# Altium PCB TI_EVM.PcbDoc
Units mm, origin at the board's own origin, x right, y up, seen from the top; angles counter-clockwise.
Board outline 90 x 58.4 mm, 2 copper layers (Top Layer, Bottom Layer); 66 components, 32 nets, 162 pads, 48 vias.
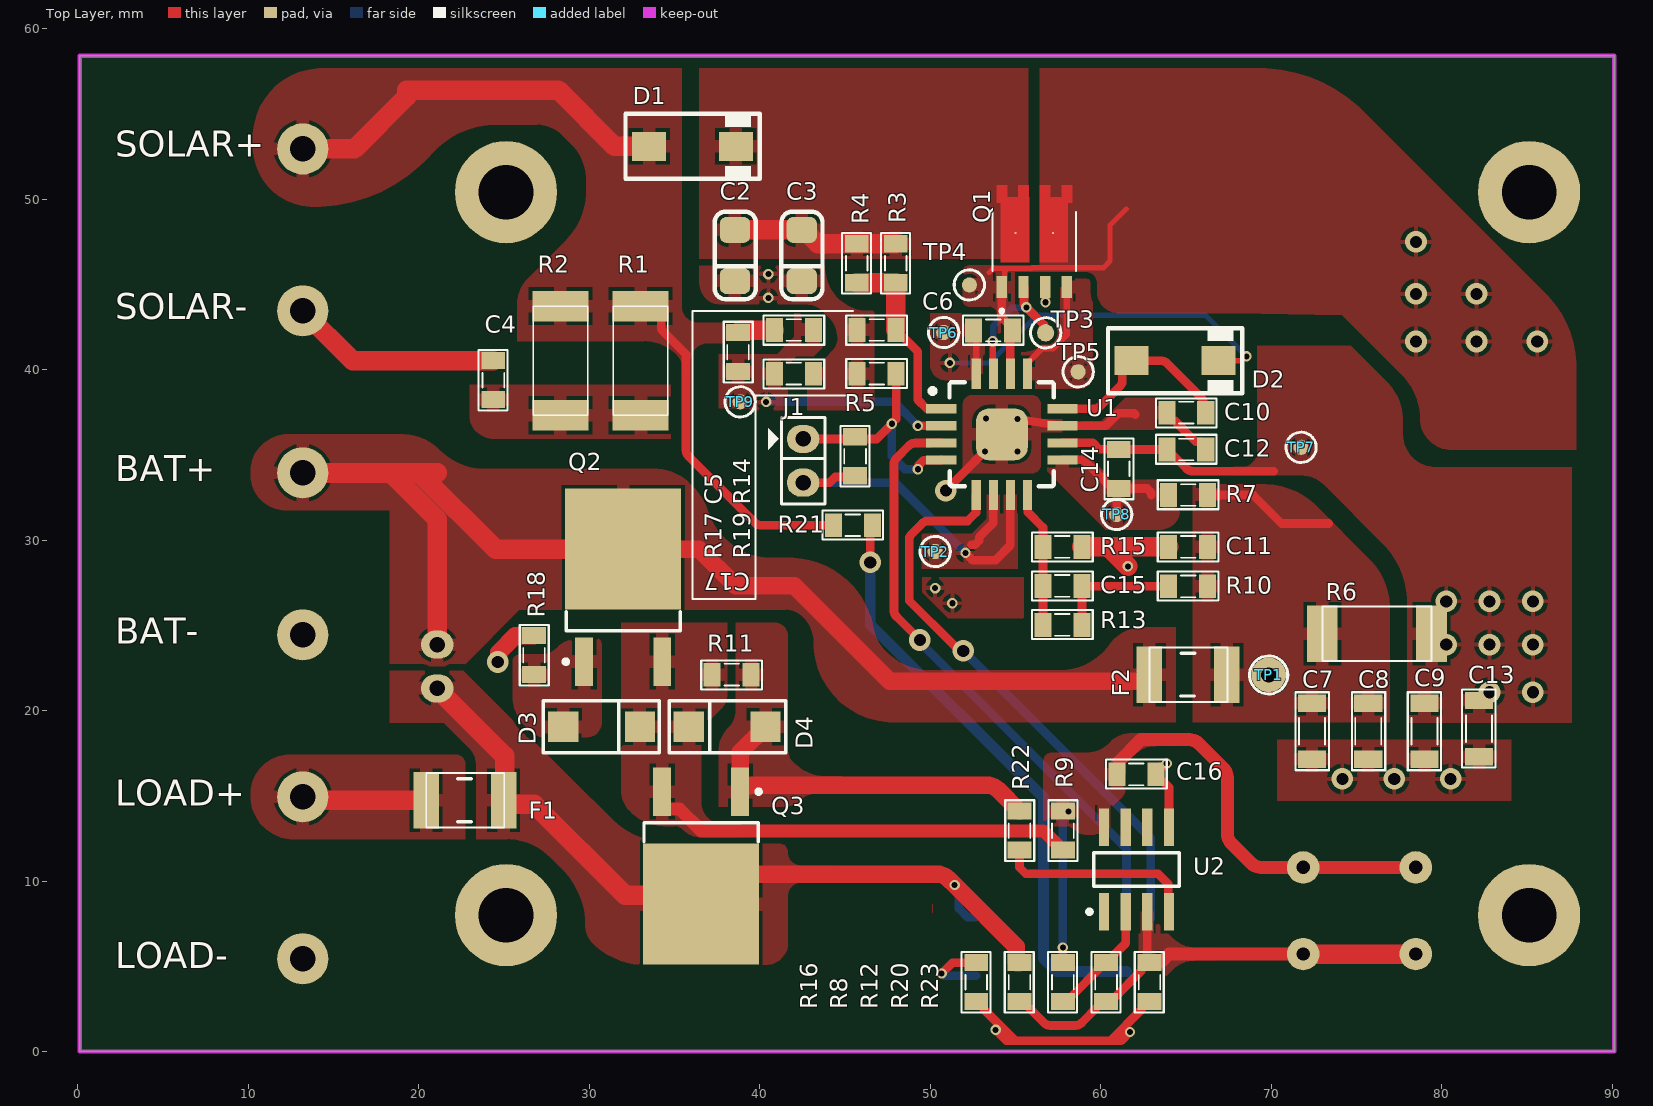
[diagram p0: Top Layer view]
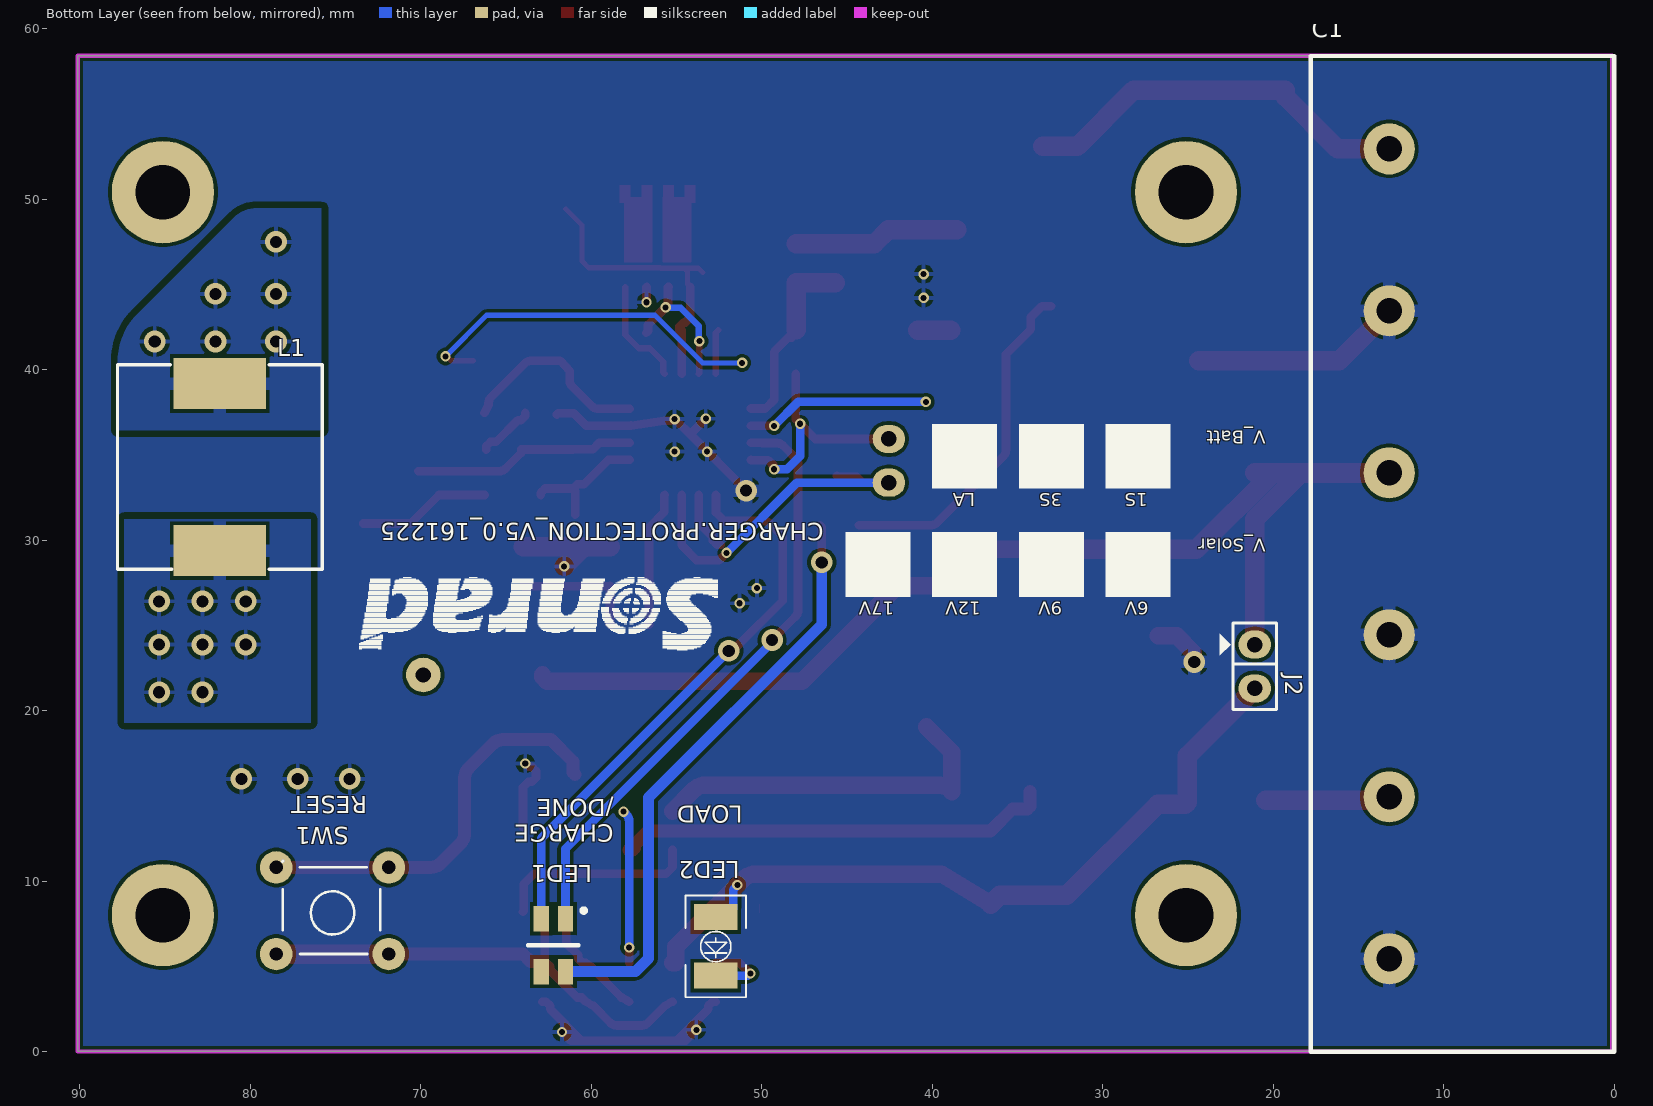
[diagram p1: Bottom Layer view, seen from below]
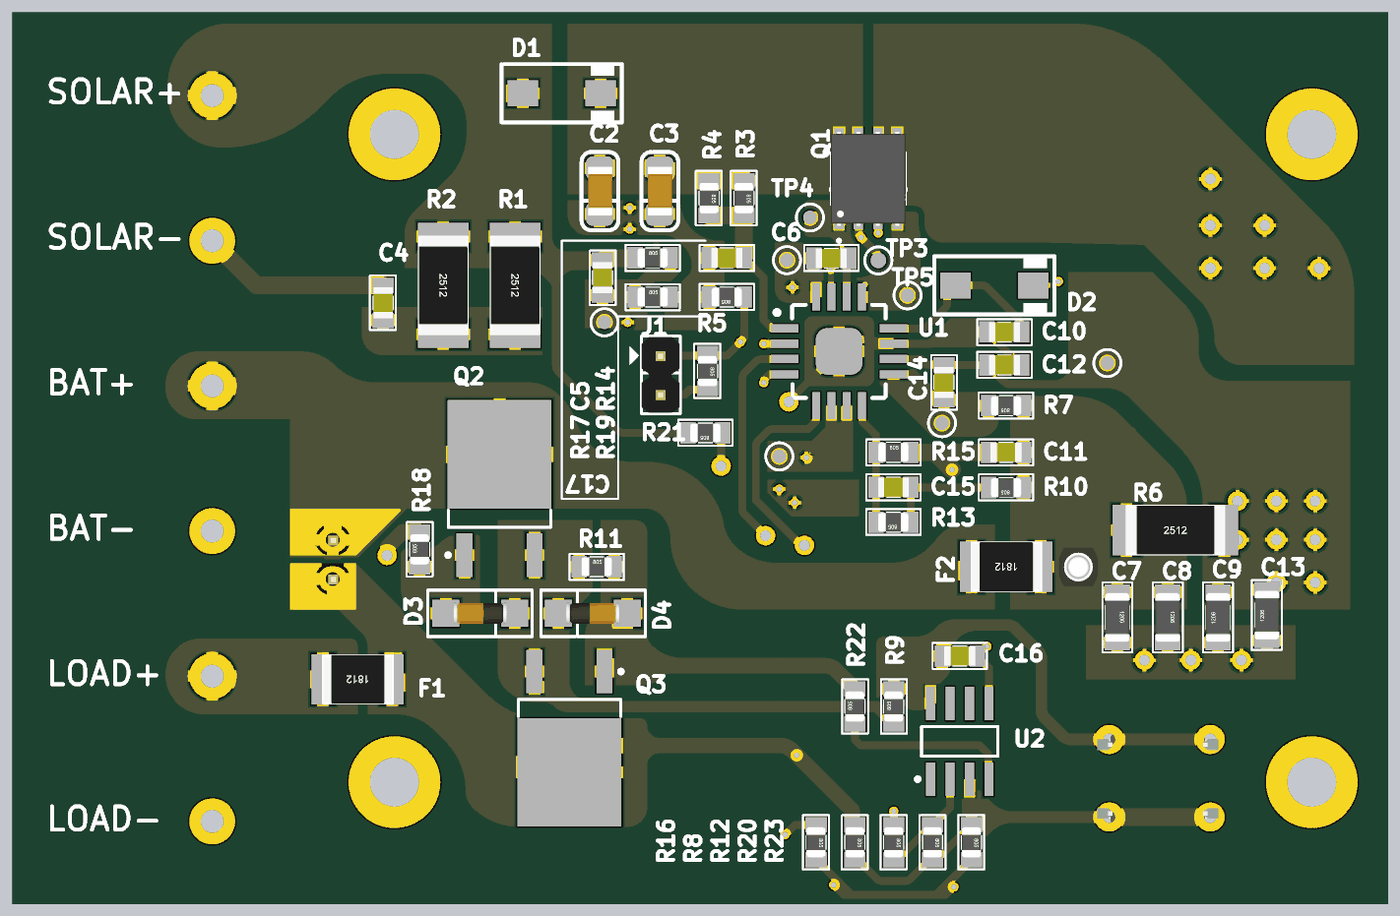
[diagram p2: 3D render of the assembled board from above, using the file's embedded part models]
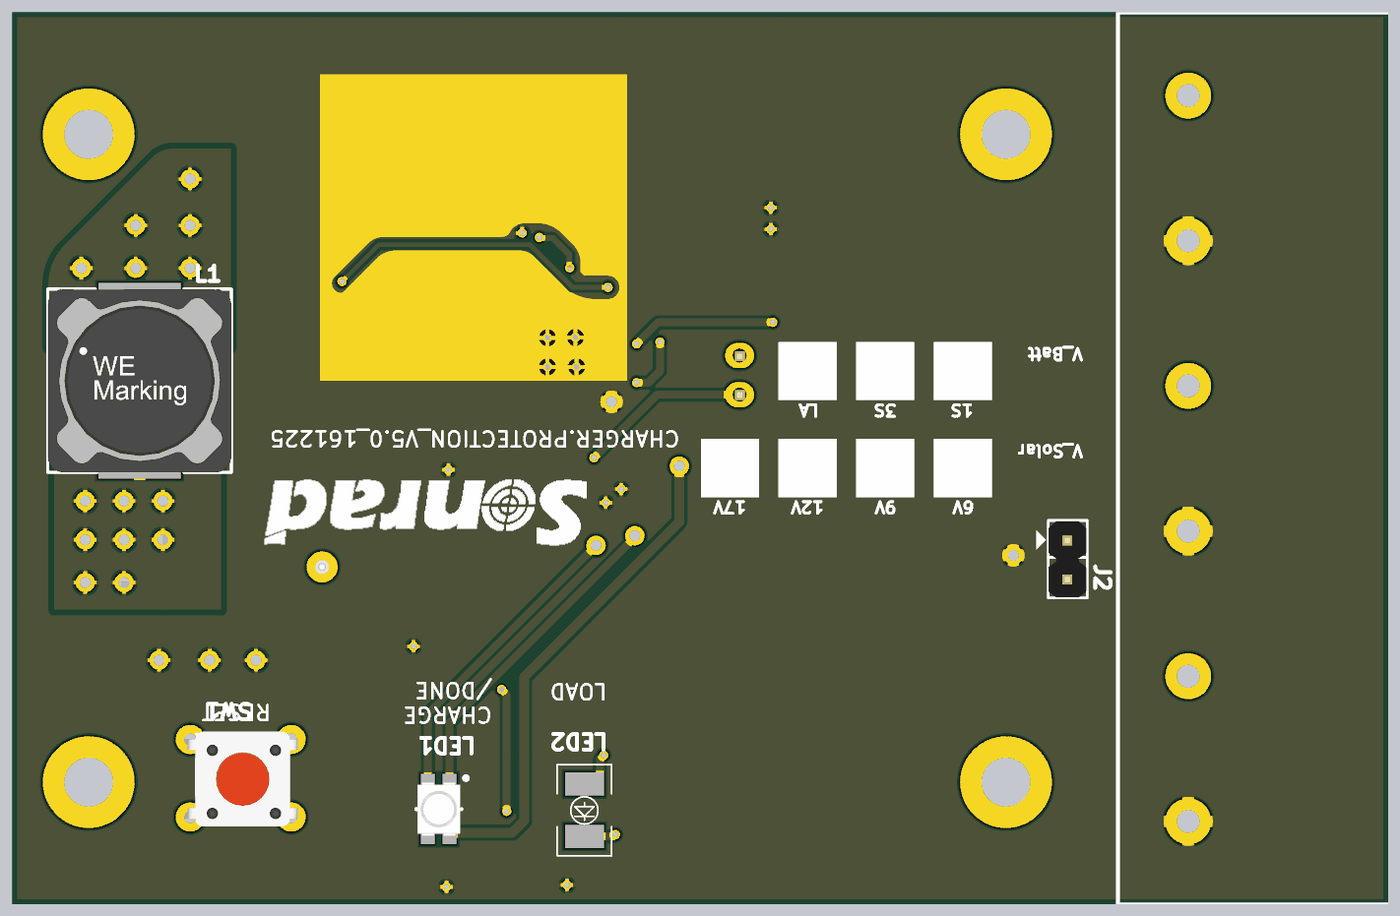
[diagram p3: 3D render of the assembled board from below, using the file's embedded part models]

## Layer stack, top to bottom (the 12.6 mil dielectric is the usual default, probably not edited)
Top Solder: solder mask 0.0102, Solder Resist, Dk 3.5
Top Layer: signal copper 0.0356
Dielectric 1: dielectric 0.32, FR-4, Dk 4.8
Bottom Layer: signal copper 0.0356
Bottom Solder: solder mask 0.0102, Solder Resist, Dk 3.5

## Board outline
0.119,0.016 0.119,58.416 90.119,58.416 90.119,0.016

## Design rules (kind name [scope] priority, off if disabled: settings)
Clearance [All] p1: gap=0.203 ignorepadtopadclearanceinfootprint=FALSE except(0: Arc-Text Track-Text SMDPad-Text SMDPad-Hole THPad-THPad THPad-Text THPad-Hole Via-Text Via-Hole Fill-Text Fill-Hole Poly-Text Poly-Hole Region-Text Region-Hole Text-Text Text-Hole; 0.305: Arc-Via Track-Via SMDPad-Via THPad-Via Via-Via; 0.381: Fill-Fill Fill-Poly Fill-Region Poly-Poly Poly-Region Region-Region)
HoleSize [All] p1: absolutevalues=TRUE maxlimit=3.81 minlimit=0.025 maxpercent=80.000 minpercent=20.000
MinimumSolderMaskSliver [All] p1: minsoldermaskwidth=0
PlaneClearance [All] p1: clearance=0.381
PlaneConnect [All] p1: planeconnectstyle=Relief reliefexpansion=0.762 reliefentries=4 reliefconductorwidth=0.254 reliefairgap=0.254
PolygonConnect [All] p1: connectstyle=Relief reliefconductorwidth=0.762 reliefentries=4 polygonreliefangle="90 Angle" airgapwidth=0.203
RoutingVias [All] p1: holewidth=0.711 width=1.27 viastyle="Through Hole" minholewidth=0.254 minwidth=0.508 maxholewidth=0.711 maxwidth=1.27
SilkToSilkClearance [All] p1: silktosilkclearance=0.025
SilkToSolderMaskClearance [IsPad] p1: minsilkscreentomaskgap=0 clearancetoexposedcopper=TRUE
SolderMaskExpansion [All] p1: expansion=0.102 istentingtop=FALSE
SupplyNets "Schematic Supply Nets_1" [InNet('TERM_EN')] p1: voltage=0.000
SupplyNets "Schematic Supply Nets_5" [InNet('GND')] p2: voltage=0.000
Width [All] p1: maxlimit=1.143 minlimit=0.254 preferedwidth=0.508 bottomlayer_minwidth=0.305 minimp=50.000000 maximp=50.000000 favimp=50.000000
24 further rules are at their usual default settings.

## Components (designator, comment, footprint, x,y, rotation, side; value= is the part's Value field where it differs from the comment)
C1 "JP6" HB9500-6P 17.8,58.4 r270 bottom locked
C2 "10uF" CAP_3216 38.6,46.752 r90 top value=33p
C3 "10uF" CAP_3216 42.515,46.752 r90 top value=33p
C4 "2.2uF" CAP_0805 24.376,39.386 r270 top value=33p
C5 "0.1uF" CAP_0805 46.855,42.332 r0 top value=33p
C6 "1uF" CAP_0805 53.691,42.307 r180 top value=33p
C7 "4.7uF" CAP_1206 72.39,18.796 r270 top value=33p
C8 "1uF" CAP_1206 75.692,18.796 r270 top value=33p
C9 "10uF" CAP_1206 78.994,18.796 r90 top value=33p
C10 "10uF" CAP_0805 65.016,37.481 r0 top value=33p
C11 "0.1uF" CAP_0805 65.121,29.607 r0 top value=33p
C12 "10uF" CAP_0805 65.016,35.322 r180 top value=33p
C13 "10uF" CAP_1206 82.185,18.953 r90 top value=33p
C14 "10uF" CAP_0805 61.057,34.179 r90 top value=33p
C15 "0.1uF" CAP_0805 57.755,27.321 r0 top value=33p
C16 "0.47uF" CAP_0805 62.095,16.272 r180 top value=33p
C17 "22pF" CAP_0805 38.727,41.037 r90 top value=33p
D1 "1N5824" SMA 36.06,53.102 r0 top value="Diode c?m 1N5408"
D2 "1N5819" SMA 64.359,40.529 r0 top value="Diode c?m 1N5408"
D3 "Zenner 12V" DIODE_ZENER_SMD 30.726,19.066 r0 top
D4 "Zenner 12V" DIODE_ZENER_SMD 38.092,19.066 r180 top
F1 "F5A" RES-SMD-1812 22.979,14.748 r180 top value=Fuse
F2 "F5A" RES-SMD-1812 65.397,22.114 r180 top value=Fuse
J1 "Jumper 2" JP2 42.545,35.941 r270 top value="JP 2"
J2 "Jumper 2" JP2 21.082,23.876 r270 bottom value="JP 2"
L1 "15uH" L-SMD-M-12x10 81.788,34.29 r180 bottom value="150 mH"
LED1 "LED RGB SMD v1" "LED RGB 3528" 62.222,6.249 r270 bottom locked
LED2 "LED" "LED 3512" 52.697,7.89 r270 bottom locked value="LED 3 - 5 ly 2 Colour"
Q1 "SI7288" "SO-8 dual" 56.104,47.517 r90 top
Q2 "Sud50p06" TO-252 31.992,27.076 r90 top
Q3 "Sud50p06" TO-252 36.564,11.056 r270 top
R1 "2R" RES-SMD-2512 32.885,40.529 r270 top
R2 "2R" RES-SMD-2512 28.186,40.529 r270 top
R3 "10R" RES-SMD-0805 47.976,46.244 r270 top
R4 "NC" RES-SMD-0805 45.69,46.244 r270 top
R5 "10k" RES-SMD-0805 45.593,34.925 r270 top
R6 "0.05" RES-SMD-2512 76.2,24.384 r0 top
R7 "0R" RES-SMD-0805 65.121,32.655 r180 top
R8 "DFN" RES-SMD-0805 55.237,4.08 r270 top
R9 "10R" RES-SMD-0805 57.777,12.97 r90 top
R10 "0R" RES-SMD-0805 65.121,27.296 r180 top
R11 "1M" RES-SMD-0805 38.346,22.114 r0 top
R12 "100k" RES-SMD-0805 57.777,4.08 r270 top
R13 "499k" RES-SMD-0805 57.755,25.035 r180 top
R14 "10k" RES-SMD-0805 46.855,39.767 r180 top
R15 "100k" RES-SMD-0805 57.755,29.607 r0 top
R16 "10k" RES-SMD-0805 52.697,4.08 r270 top
R17 "499k" RES-SMD-0805 42.007,42.332 r0 top
R18 "100k" RES-SMD-0805 26.764,23.257 r90 top
R19 "36k" RES-SMD-0805 42.007,39.767 r0 top
R20 "1M" RES-SMD-0805 60.317,4.08 r270 top
R21 "1k" RES-SMD-0805 45.458,30.877 r180 top
R22 "100R" RES-SMD-0805 55.237,12.97 r90 top
R23 "115k" RES-SMD-0805 62.857,4.08 r270 top
SW1 "SW" SW4 71.874,5.731 r0 bottom locked value="Button chip 4 pin"
TP1 "TP" TP1 69.85,22.098 r0 top value="Test Point"
TP2 "TP" "Testpoint 50ml"#1 50.292,29.337 r0 top value="Test Point"
TP3 "TP" "Testpoint 50ml"#2 56.769,42.164 r0 top value="Test Point"
TP4 "TP" "Testpoint 50ml"#1 52.294,44.974 r0 top value="Test Point"
TP5 "TP" "Testpoint 50ml"#1 58.674,39.878 r0 top value="Test Point"
TP6 "TP" "Testpoint 50ml"#1 50.792,42.18 r0 top value="Test Point"
TP7 "TP" "Testpoint 50ml"#1 71.747,35.449 r0 top value="Test Point"
TP8 "TP" "Testpoint 50ml"#1 60.93,31.512 r0 top value="Test Point"
TP9 "TP" "Testpoint 50ml"#1 38.854,38.116 r0 top value="Test Point"
U1 "BQ24650" VQFN-16 54.199,36.211 r270 top
U2 "MAX8212" SOIC-8 62.095,10.684 r90 top

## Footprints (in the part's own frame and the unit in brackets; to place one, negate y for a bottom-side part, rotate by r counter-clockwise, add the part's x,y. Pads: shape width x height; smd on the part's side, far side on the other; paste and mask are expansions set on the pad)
CAP_0805 [mil]
  rect 39.37x55 smd: 1(-45,0) 2(45,0)
  silkscreen extent -70,-34 70,33, body extent -40,-25 40,25, height 24
CAP_1206 [mil]
  rect 40x65 smd: 1(-65,0) 2(65,0)
  silkscreen extent -90,-38 90,39, body extent -63,-31 63,32, height 40
CAP_3216 [mil]
  rrect50% 60x70 smd: 1(-60.99,2) 2(56.99,2)
  silkscreen extent -103,-46 99,49, body extent -65,-30 61,32, height 39
DIODE_ZENER_SMD [mil]
  rect 70x70 smd: 1(-88.58,0) 2(88.58,0)
  silkscreen extent -135,-60 134,60, body extent -69,-29 69,29, height 57
HB9500-6P [mm]
  round 3 hole 1.5: 1(5.45,4.6) 2(14.95,4.6) 3(24.45,4.6) 4(33.95,4.6) 5(43.45,4.6) 6(52.95,4.6)
  silkscreen extent 0,0 58.4,17.8
JP2 [mil]
  oval 65x75 hole 36: 1(0,0) 2(101,0)
  silkscreen extent -50,-81 150,50, body extent -48,-50 148,48, height 323
L-SMD-M-12x10 [mm] "WE-PDA SMD Shielded Power Inductor, 1210"
  rect 5.4x3 smd: 1(0,4.9) 2(0,-4.9)
  silkscreen extent -6,-6 6,6, body extent -6,-6 6,6, height 9.7
"LED 3512" [mil]
  rect 60x100 smd: 1(-0.2,0) 2(134.8,0)
  silkscreen extent -50,-70 185,70, body extent -20,-60 155,60, height 75
"LED RGB 3528" [mm]
  rect 1.5x0.9 smd: 1(1.55,0.707) 2(1.55,-0.71) 3(-1.55,0.707) 4(-1.55,-0.707)
  silkscreen extent -2.15,-1.5 0.03,1.9, body extent -1.75,-1.4 1.75,1.4, height 1.87
RES-SMD-0805 [mil]
  rect 39.37x55 smd: 1(-45,0) 2(45,0)
  silkscreen extent -70,-34 70,33, body extent -39,-25 39,25, height 31
RES-SMD-1812 [mm] "Chip Capacitor, Body 3.2x2.5mm, IPC Medium Density"
  rect 1.5x3.3 smd: 1(-1.996,0) 2(2.54,0)
  silkscreen extent -2.04,-1.6 2.54,1.6, body extent -2,-1.6 2.5,1.6, height 0.6
RES-SMD-2512 [mm] "Chip Capacitor, Body 3.2x2.5mm, IPC Medium Density"
  rect 1.8x3.3 smd: 1(-3.2,0.127) 2(3.2,0.127)
  silkscreen extent -3.2,-1.47 3.2,1.73, body extent -3.2,-1.47 3.2,1.73, height 0.6
SMA [mm]
  rect 2x1.7 smd: 1(-2.544,0) 2(2.544,0)
  silkscreen extent -3.94,-1.9 3.94,1.91, body extent -2.87,-1.4 2.87,1.4, height 2.29
"SO-8 dual" [mm] "Dual N-channel"
  rect 1.27x0.61 smd: 1(-2.67,1.905) 2(-2.67,0.635) 3(-2.67,-0.635) 4(-2.67,-1.905)
  rect 0.1x0.1 smd paste-1 mask+0: 5_6_10(0.5,-1.1) 7_8_9(0.5,1.1)
  Top Layer region: 2.6,-0.33 3.305,-0.33 3.305,-0.94 2.6,-0.94 2.6,-1.6 3.305,-1.6 3.305,-2.21 2.285,-2.21 2.285,-1.955 -1.215,-1.955 -1.215,-0.305 2.6,-0.305
  Top Layer region: 3.305,1.6 2.6,1.6 2.6,0.94 3.305,0.94 3.305,0.33 2.6,0.33 2.6,0.305 -1.215,0.305 -1.215,1.955 2.285,1.955 2.285,2.21 3.305,2.21
  silkscreen extent -4.17,-2.45 1.72,2.45, body extent -3.07,-2.58 3.07,2.58, height 1.12
SOIC-8 [mm] "SOIC, 8-Leads, Body 5,0x4,0mm (max), Pitch 1,27mm, IPC Medium Density"
  rect 2.2x0.6 smd: 1(-2.475,1.905) 2(-2.475,0.635) 3(-2.475,-0.635) 4(-2.475,-1.905) 5(2.475,-1.905) 6(2.475,-0.635) 7(2.475,0.635) 8(2.475,1.905)
  silkscreen extent -2.6,-2.5 0.98,2.88, body extent -3.2,-2.5 3.2,2.5, height 1.75
SW4 [mil] "SW button 4pin, 250 x250 mil"
  round 75 hole 31: 1(0,0) 2(0,-200) 3(260,-200) 4(260,0)
  silkscreen extent 20,-215 245,0, body extent -31,-220 281,24, height 276
"Testpoint 50ml"#1 [mil]
  round 35 smd: 1(0,0)
  silkscreen extent -35,-35 35,35
"Testpoint 50ml"#2 [mil]
  round 40 smd: 1(0,0)
  silkscreen extent -35,-35 35,35
TO-252 [mm] "KVU D-PAK, 3-Pads, Body 6,2x6,7mm (max), IPC Medium Density"
  rect 2.85x1.05 smd: 1(-4.2,2.29) 3(-4.2,-2.29)
  rect 7.1x6.8 smd: 2(2.4,0)
  silkscreen extent -4.32,-3.35 -1.27,3.49, body extent -5.03,-3.35 5.08,3.35, height 2.4
TP1 [mil] "Test point"
  round 80 hole 35: 1(0,0)
  silkscreen extent -44,-44 44,44, body extent -50,-50 50,50, height 178
VQFN-16 [mil]
  rect 21x70 smd: 1(-59.05,-140) 2(-19.68,-140) 3(19.69,-140) 4(59.06,-140) 9(59.06,140) 10(19.69,140) 11(-19.68,140) 12(-59.05,140)
  rect 70x21 smd: 5(140,-59.05) 6(140,-19.68) 7(140,19.69) 8(140,59.06) 13(-140,59.06) 14(-140,19.69) 15(-140,-19.68) 16(-140,-59.05)
  rrect50% 120x120 smd: 17(0,0)
  silkscreen extent -120,-164 120,120, body extent -118,-118 118,118, height 31

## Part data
C1: "WR-PHD 2.54 mm Angled Socket Header", Manufacturer="W¨¹rth Elektronik eiSos GmbH", partNo=613006143121
C2 C3: library part CapSMD, "Capacitor"
C4 C5 C6 C10 C11 C12 C14 C15 C16 C17: library part CapSMD, "C_0805"
C7 C8 C9 C13: library part CapSMD, "C_1206"
D1: library part 1N5822, "SS54 Diode Schottky 5A 40V"
D2: library part 1N5822, "S4 Diode Schottky 1A 40V"
D3 D4: library part Zenner, "generic zenner diode"
F1 F2: library part Fuse, "Fuse 5A"
J1 J2: library part "JP 2"
L1: library part Inductor, "Inductor"
LED2: library part "LED SMD"
Q1: library part "Dual MOSFET-N", "Si7288"
Q2 Q3: library part MOSFET-P
R1 R2 R6: library part "Resistor - SMD", "R_2512", Manufacturer="Generic Components"
R3 R4 R5 R7 R8 R9 R10 R11 R12 R13 R14 R15 R16 R17 R18 R19 R20 R21 R22 R23: library part "Resistor - SMD", "R_0805", Manufacturer="Generic Components"
SW1: library part SW4, "Switch button 4 pin"
TP1: library part TP1, "Test Point"
TP2 TP3 TP4 TP5 TP6 TP7 TP8 TP9: library part TP_1, "Test Point"
U1: "BQ24650 Stand-Alone Synchronous Buck Battery Charge Controller for Solar Power / With Maximum Power Point Tracking"
U2: "Microprocessor Voltage Monitors  / with Programmable Voltage Detection"

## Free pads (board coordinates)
  round 6 hole 3.2: 14(25.119,8.016) 14(25.119,50.416) 14(85.119,8.016) 14(85.119,50.416)

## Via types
v1: diameter 0.61, hole 0.356, Top Layer to Bottom Layer, 26 vias
v2: diameter 1.27, hole 0.711, Top Layer to Bottom Layer, 22 vias

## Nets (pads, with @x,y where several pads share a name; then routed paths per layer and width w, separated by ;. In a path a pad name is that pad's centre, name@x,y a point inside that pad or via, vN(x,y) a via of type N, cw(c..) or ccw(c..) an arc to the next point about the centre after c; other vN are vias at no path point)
BTST: C6.2 D2.2 TP6.1 U1.16 | length 23.9
  Top Layer w0.305: D2.2 68.231,40.529 68.485,40.783 v1(68.55,40.783)
  Top Layer w0.381: C6.2 52.699,42.156 U1.16
  Bottom Layer w0.305: v1(51.151,40.402) 53.459,40.402 56.253,43.196 66.137,43.196 v1(68.55,40.783)
GND: C1.2 C1.4 C1.6 C2.1 C3.1 C4.1 C5.1 C7.2 C8.2 C9.1 C10.1 C11.1 C12.1 C13.1 C16.1 Q1.3 R14.2 R15.2 R16.2 R18.2 R19.2 R23.2 U1.11 U1.17 U2.5 | length 60.6
  Top Layer w0.508: v2(50.919,32.909) 50.919,32.931 U1.17 ; R16.2 52.895,2.937 53.141,2.691 53.141,2.493 54.983,0.651 ; v1(53.282,37.128) U1.17 ; v1(53.84,1.286) 54.475,0.651 54.983,0.651 ; U1.17@54.998,37.01 U1.17@55.015,37.01 ; v1(55.11,37.1) U1.17@55.015,37.01 ; Q1.3 56.761,44.825 v1(56.761,43.958) ; v1(61.714,1.159) 61.206,0.651 60.571,0.651 ; 62.016,37.375 61.952,37.439 61.908,37.439 61.9,37.447 61.023,37.447 60.287,36.711 U1.11 57.669,36.724 55.732,37.008 55.706,37.009 ccw(c55.685,36.502) 55.685,37.01 55.11,37.01 U1.17@55.015,37.01 ; R23.2 62.659,2.937 62.412,2.691 62.412,2.493 60.571,0.651 ; v1(63.873,16.907) 63.846,16.907 63.655,16.717 63.484,16.717 63.238,16.471 C16.1 63.238,16.074 63.484,15.828 63.683,15.828 64,15.51 U2.5 ; C10.1 63.873,37.283 64.119,37.037 64.317,37.037 65.587,35.767 65.913,35.767 66.159,35.521 C12.1 ; U1.17 54.961,36.959 U1.17@55.015,37.01 ; 54.983,0.651 60.571,0.651
  Top Layer w1.016: v2(24.638,22.86) 24.687,22.909 24.687,23.417 25.67,24.4 R18.2
  Top Layer w1.143: C1.2 16.121,40.529 C4.1 ; R15.2 60.571,29.607 ; v1(61.587,28.464) 60.571,29.48 60.571,29.607 ; C11.1 60.571,29.607
  other v1: 51.3,26.305 50.284,27.194 53.205,35.195 55.11,35.195 40.505,44.212 40.505,45.609
  other v2: 74.168,16.002 77.216,16.002 80.518,16.002
HIDRV: Q1.2 TP3.1 U1.15 | length 8.4
  Top Layer w0.381: v1(53.658,41.678) 53.679,41.658 53.679,39.788 U1.15
  Top Layer w0.508: Q1.2 55.498,44.818 55.498,43.83 55.64,43.688 v1(55.64,43.66) ; v1@55.659,43.641 56.672,42.628 56.672,42.261 TP3.1
  Bottom Layer w0.381: v1(53.658,41.678) 53.685,41.706 53.685,42.555 54.763,43.633 55.613,43.633 v1(55.64,43.66)
LODRV: Q1.4 TP5.1 U1.13 | length 6.4
  Top Layer w0.381: U1.13 55.776,39.843 55.776,40.466 56.57,41.26 57.215,41.26 58.009,42.054 Q1.4
MPPSET: C17.1 R17.2 R19.1 TP9.1 U1.2 | length 10.9
  Top Layer w0.508: v1(49.276,36.703) 49.284,36.711 U1.2
  Bottom Layer w0.508: v1(40.378,38.116) 47.863,38.116 v1(49.276,36.703)
NetC1_5: C1.5 F1.2 | length 7.4
  Top Layer w1.143: C1.5 13.2,14.748 F1.2
NetC2_2: C2.2 C3.2 D1.2 Q1.7_8_9 R3.1 R4.1 | length 9.8
  Top Layer w1.143: C2.2 C3.2 42.591,48.2 43.404,47.387 R4.1 R3.1
NetC4_2: C4.2 R1.2 R2.2
NetC5_2: C5.2 R3.2 R4.2 U1.1 | length 11.4
  Top Layer w0.508: C5.2@47.976,42.354 47.976,42.156 48.244,41.888 48.442,41.888 49.268,41.062 49.268,38.243 49.787,37.724 50.63,37.724 U1.1
  Top Layer w1.143: R4.2 R3.2 C5.2@47.976,42.354
NetC7_1: C7.1 C8.1 C11.2 F2.1 R6.1 R7.1 R10.1 TP1.1 | length 7.8
  Top Layer w0.508: R7.1 68.931,32.655 70.607,30.979 73.376,30.979
NetC10_2: C10.2 D2.1 U1.12 | length 11.6
  Top Layer w0.508: U1.12 59.598,37.711 ccw(c59.598,38.219) 59.903,37.812 ccw(c59.598,38.219) 59.957,37.859 61.119,39.021 ccw(c60.759,39.379) 61.267,39.379 61.267,39.933 D2.1 63.528,40.529 cw(c63.528,40.021) 63.886,40.381 65.878,38.389 cw(c65.518,38.031) 66.026,38.031 66.026,37.926 C10.2@66.264,37.481
NetC15_1: C15.1 R13.2 R15.1 U1.8 | length 8
  Top Layer w0.508: U1.8 55.712,32.642 55.712,31.65 56.612,30.75 R13.2
NetC15_2: C15.2 R10.2 R13.1 | length 7.3
  Top Layer w0.508: R13.1 58.898,26.851 C15.2 ; C15.2@58.924,27.296 R10.2
NetC16_2: C16.2 R9.2 R12.1 SW1.2 SW1.3 U2.8 | length 33
  Top Layer w0.508: R12.1 v1(57.777,6.112)
  Top Layer w0.762: C16.2 61.071,16.391 61.071,17.026 62.349,18.304 65.2,18.304 cw(c65.2,17.542) 65.658,18.152 cw(c65.2,17.542) 65.739,18.081 67.206,16.614 cw(c66.667,16.075) 67.277,16.533 cw(c66.667,16.075) 67.429,16.075 67.429,12.77 ccw(c68.191,12.77) 67.581,12.312 ccw(c68.191,12.77) 67.652,12.231 68.849,11.034 ccw(c69.388,11.573) 68.93,10.963 ccw(c69.388,11.573) 69.388,10.811 SW1.2 SW1.3
  Bottom Layer w0.508: v1(57.777,6.112) 57.777,13.537 cw(c58.285,13.537) 57.925,13.896 v1@58.091,14.062
  other v1: 58.111,14.082
NetD3_1: D3.1 Q2.1 R18.1
NetD3_2: D3.2 D4.2 Q2.3 Q3.3 R9.1 R11.1 | length 25.6
  Top Layer w0.762: Q3.3 34.274,14.379 34.418,14.235 35.295,14.235 36.573,12.957 56.647,12.957 57.459,12.144 57.459,11.946 57.579,11.827 R9.1
NetD4_1: D4.1 Q3.1 R11.2 R22.2 | length 21.5
  Top Layer w1.016: Q3.1@38.854,15.62 Q3.1 38.871,15.401 39.278,15.564 cw(c39.656,14.621) 39.656,15.637 53.292,15.637 cw(c53.292,14.621) 54.011,15.339 R22.2 ; Q3.1@38.854,15.637 38.854,17.578 D4.1
NetJ1_1: J1.1 R5.1 R14.1 U1.4 | length 14.1
  Top Layer w0.508: J1.1 46.863,35.941 v1(47.752,36.83) 47.752,36.857 47.998,37.104 R14.1 ; v1(49.276,34.163) 49.295,34.182 49.295,34.369 49.624,34.698 50.63,34.698 U1.4
  Bottom Layer w0.508: v1(47.752,36.83) 47.752,34.925 48.514,34.163 v1(49.276,34.163)
NetLED1_1: LED1.1 R21.1 | length 34.9
  Top Layer w0.508: v2(46.482,28.702) 46.482,30.758 R21.1
  Bottom Layer w0.635: v2(46.482,28.702) 46.482,25.062 56.634,14.91 56.634,5.477 57.412,4.699 LED1.1
NetLED1_3: LED1.3 U1.3 | length 35.7
  Top Layer w0.508: v2(49.395,24.146) 48.02,25.521 48.019,25.522 cw(c48.379,25.88) 47.973,25.576 cw(c48.379,25.88) 47.871,25.88 47.871,34.453 cw(c48.379,34.453) 47.973,34.757 cw(c48.379,34.453) 48.019,34.811 48.758,35.55 cw(c49.117,35.19) 49.117,35.698 50.008,35.698 U1.3
  Bottom Layer w0.508: v2(49.395,24.146) 49.395,24.019 55.64,17.774 61.514,11.899 LED1.3
NetLED1_4: LED1.4 U1.5 | length 33.9
  Top Layer w0.508: v2(51.935,23.511) 51.729,23.511 51.357,23.882 51.347,23.882 48.76,26.469 48.76,30.008 cw(c49.268,30.008) 48.862,30.312 cw(c49.268,30.008) 48.908,30.366 49.525,30.983 cw(c49.883,30.623) 49.579,31.029 cw(c49.883,30.623) 49.883,31.131 52.189,31.131 52.687,31.629 52.687,32.642 U1.5
  Bottom Layer w0.508: v2(51.935,23.511) 62.929,12.517 LED1.4
NetLED2_2: LED2.2 R16.1 | length 4.4
  Top Layer w0.508: v1(50.665,4.588) 51.3,5.223 R16.1
  Bottom Layer w0.508: v1(50.665,4.588) 50.692,4.588 50.814,4.466 LED2.2
NetR8_2: R8.2 R20.2 R23.1 SW1.1 SW1.4 U2.3 | length 28.6
  Top Layer w0.508: R8.2 55.681,2.691 56.685,1.688 ccw(c57.043,2.048) 56.738,1.642 ccw(c57.043,2.048) 57.043,1.54 58.511,1.54 ccw(c58.511,2.048) 58.816,1.642 ccw(c58.511,2.048) 58.869,1.688 59.872,2.691 R20.2 60.563,3.183 60.817,3.183 62.412,4.779 62.412,4.977 62.659,5.223 R23.1 62.73,5.35 U2.3
  Top Layer w0.762: R23.1 62.917,5.283 63.552,5.283 64,5.731 SW1.1
  Top Layer w1.143: SW1.1 SW1.4
NetR12_2: R12.2 R20.1 U2.2 | length 7
  Top Layer w0.508: R12.2 58.221,3.183 60.015,4.977 R20.1 60.515,5.223 60.761,5.469 60.761,5.668 61.46,6.366 U2.2
NetR22_1: R22.1 U2.4 | length 11.8
  Top Layer w0.508: R22.1 55.237,10.811 55.618,10.43 63.365,10.43 63.954,9.841 63.954,8.255 U2.4
PH: C6.1 L1.1 Q1.1 Q1.5_6_10 TP4.1 U1.14 | length 17.6
  Top Layer w0.305: 53.462,45.697 53.712,45.946 54.537,45.946 ; Q1.1 54.352,45 54.352,45.762 54.537,45.946 ; 61.491,49.419 60.549,48.477 60.549,46.371 60.158,45.98 55.98,45.98 55.946,45.946 54.537,45.946
  Top Layer w0.508: Q1.1 54.199,43.049 54.497,42.752 54.588,42.752 54.834,42.506 C6.1 54.699,42.307 U1.14
  other v2: 78.486,41.656 82.042,41.656 85.598,41.656 78.486,44.45 82.042,44.45 78.486,47.498
SRN: C14.1 R7.2 TP8.1 U1.9 | length 7.7
  Top Layer w0.508: U1.9 59.001,34.711 60.43,33.282 60.811,33.282 C14.1 ; TP8.1 60.93,32.909 C14.1 ; 62.962,32.655 62.962,32.79 62.716,33.036 C14.1
SRP: C9.2 C12.2 C13.2 C14.2 L1.2 R6.2 TP7.1 U1.10 | length 13.2
  Top Layer w0.508: U1.10 59.525,35.711 59.894,35.342 61.037,35.342 C14.2 64.105,35.322 64.105,35.123 64.119,35.11 65.029,34.2 ccw(c65.387,34.56) 65.082,34.154 ccw(c65.387,34.56) 65.387,34.052 70.14,34.052
  other v2: 82.804,21.082 85.344,21.082 80.264,23.876 82.804,23.876 85.344,23.876 80.264,26.416 82.804,26.416 85.344,26.416
TERM_EN: J1.2 R5.2 TP2.1 U1.6 U1.7 | length 24.1
  Top Layer w0.508: J1.2 44.094,33.376 44.43,33.711 45.522,33.711 R5.2 ; v1(52.07,29.254) 52.495,28.829 53.824,28.829 54.699,29.704 U1.7 ; 52.421,29.734 52.62,29.734 52.866,29.98 52.866,30.178 53.699,31.012 U1.6
  Bottom Layer w0.508: J1.2 47.949,33.376 v1(52.07,29.254)
V_BATT: C1.3 F2.2 J2.1 Q2.2 | length 79.2
  Top Layer w1.016: Q2.2 36.441,29.476 38.596,27.321 42.029,27.321 47.617,21.733 62.615,21.733 62.857,21.975 F2.2
  Top Layer w1.143: J2.1 21.082,31.242 18.374,33.95 C1.3 ; 21.082,33.95 C1.3 ; Q2.2 24.507,29.476 20.058,33.925 13.225,33.925 C1.3
V_LOAD: F1.1 J2.2 LED2.1 Q3.2 R8.1 | length 46.8
  Top Layer w1.016: Q3.2 39.456,10.414 50.378,10.414 cw(c50.376,9.398) 51.09,10.12 v1(51.435,9.779) 55.046,6.168 55.046,5.231 55.054,5.223 R8.1
  Top Layer w1.143: J2.2 25.04,17.352 25.04,14.626 25.153,14.513 26.77,14.513 32.119,9.164 36.056,9.164 Q3.2
  Bottom Layer w0.508: v1(51.435,9.779) 51.435,9.752 51.681,9.506 51.681,8.403 52.189,7.895 LED2.1
V_SOLAR: C1.1 C17.2 D1.1 R1.1 R2.1 R17.1 R21.2 | length 45.7
  Top Layer w0.508: R1.1 33.579,43.729 34.225,43.083 34.225,42.364 35.679,40.91 35.679,35.277 ccw(c36.187,35.278) 35.827,34.92 39.723,31.024 ccw(c40.08,31.385) 40.078,30.877 R21.2
  Top Layer w1.143: C1.1 16.223,52.95 19.296,56.023 19.296,56.404 28.186,56.404 31.488,53.102 D1.1 ; C17.2@38.91,42.307 R17.1@40.864,42.307
pads on no net: LED1.2 U2.1 U2.6 U2.7

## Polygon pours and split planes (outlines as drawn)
PH on Top Layer "PH_L01_P000" (solid, pour order 0): 78.74,37.146 ccw(c75.21,37.146) 77.706,39.642 74.168,43.18 67.818,43.323 61.057,43.323 cw(c61.057,44.593) 59.787,44.593 59.787,45.101 ccw(c59.152,45.101) 59.152,45.736 54.961,45.736 54.961,44.011 ccw(c56.008,44.011) 55.268,43.27 55.469,43.069 55.469,41.418 54.961,41.418 54.961,40.021 54.453,40.021 54.453,41.418 53.945,41.418 53.945,43.196 ccw(c53.437,43.196) 53.437,43.704 52.294,43.704 cw(c52.294,44.085) 51.913,44.085 51.913,45.736 cw(c52.294,45.736) 52.294,46.117 56.434,46.117 56.434,57.674 68.169,57.674 69.285,57.674 cw(c69.285,48.991) 75.425,55.131 86.044,44.512 cw(c81.603,40.07) 87.884,40.07 87.884,35.306 80.58,35.306 cw(c80.58,37.146)
V_LOAD on Top Layer "NONET_L01_P-001" (solid, pour order 29): 21.471,19.304 18.288,19.304 18.288,22.352 22.614,22.352 24.162,20.804 29.031,15.935 31.278,13.688 ccw(c34.852,17.263) 34.852,12.208 41.132,12.208 cw(c41.132,11.692) 41.648,11.692 ccw(c42.418,11.692) 42.418,10.922 44.442,10.922 44.442,9.906 42.418,9.906 ccw(c42.418,9.136) 41.648,9.136 41.648,6.366 cw(c40.378,6.366) 40.378,5.096 33.249,5.096 cw(c33.249,9.348) 30.242,6.342 cw(c31.374,7.474) 29.773,7.474 ccw(c25.244,7.474) 28.446,10.678 27.709,11.415 ccw(c25.182,8.89) 25.182,12.462 23.36,12.462 23.36,16.86 ccw(c22.019,16.86) 22.967,17.808
V_BATT on Top Layer "NONET_L01_P-001" (solid, pour order 47): 22.606,22.606 25.908,25.908 20.05,31.766 18.293,31.766 18.293,22.611 18.288,22.606
V_BATT on Top Layer "NONET_L01_P-001" (solid, pour order 32): 40.685,28.972 41.713,28.972 cw(c41.714,23.918) 45.287,27.492 cw(c41.716,23.92) 46.623,25.118 ccw(c49.225,25.342) 47.378,23.496 ccw(c50.101,26.218) 50.101,22.368 57.561,22.368 ccw(c57.561,26.014) 60.532,23.901 cw(c62.453,22.536) 62.453,24.892 64.389,24.892 64.389,19.32 47.858,19.32 cw(c47.858,24.006) 43.172,24.006 ccw(c41.07,24.006) 42.556,25.493 ccw(c41.516,24.454) 41.516,25.924 25.011,25.924 20.215,30.72 ccw(c18.294,29.479) 18.293,31.766 12.184,31.766 cw(c12.184,33.798) 10.152,33.798 10.152,34.052 cw(c12.311,34.052) 12.311,36.211 19.011,36.211 cw(c19.012,33.073) 21.232,35.291 ccw(c23.917,37.976) 23.917,34.179 33.87,34.179 cw(c33.871,31.347) 35.874,33.349 36.062,33.161 cw(c33.465,30.563) 36.919,31.814 ccw(c44.236,34.467) 37.149,31.25 ccw(c40.685,32.856)
GND on Top Layer "NONET_L01_P-001" (solid, pour order 46): 84.074,18.288 70.358,18.288 70.358,14.732 84.074,14.732
NetC7_1 on Top Layer "NONET_L01_P-001" (solid, pour order 20): 72.688,31.968 75.73,28.926 cw(c72.755,25.952) 76.962,25.952 76.962,19.32 65.397,19.32 65.397,33.29 69.496,33.29 cw(c69.496,28.775)
BTST on Top Layer "NONET_L01_P-001" (solid, pour order 2): 50.008,43.323 50.008,40.275 ccw(c50.897,40.275) 50.897,39.386 53.183,39.386 53.183,43.323
NetC2_2 on Top Layer "NONET_L01_P-001" (solid, pour order 3): 36.441,57.674 36.441,46.498 55.745,46.498 55.745,57.674
GND on Top Layer "NONET_L01_P-001" (solid, pour order 5): 51.913,37.989 51.913,34.306 ccw(c52.294,34.306) 52.294,33.925 55.977,33.925 ccw(c55.977,34.433) 56.485,34.433 56.485,36.465 63.724,36.465 63.724,38.37 61.438,38.37 60.041,36.973 56.485,36.973 56.485,37.989 ccw(c55.977,37.989) 55.977,38.497 52.421,38.497 ccw(c52.421,37.989)
SRN on Top Layer "NONET_L01_P-001" (solid, pour order 6): 64.635,33.544 64.635,31.766 cw(c63.492,31.766) 63.492,30.623 60.295,30.623 56.866,34.052 56.866,35.068 59.152,35.068 60.676,33.544
TERM_EN on Top Layer "NONET_L01_P-001" (solid, pour order 8): 55.118,33.671 55.118,28.337 49.5,28.337 49.5,30.369 52.421,30.369 53.31,31.258 53.31,33.671
SRP on Top Layer "NONET_L01_P-001" (solid, pour order 9): 78.268,34.859 ccw(c79.641,36.232) 79.641,34.29 87.63,34.29 87.63,19.304 77.978,19.304 77.978,26.354 ccw(c73.11,26.354) 76.552,29.796 73.125,33.223 ccw(c71.738,31.836) 71.738,33.798 67.788,33.798 67.788,34.306 68.296,34.306 ccw(c68.296,35.195) 69.185,35.195 69.185,41.402 74.676,41.402 76.751,39.327 cw(c74.401,36.978) 77.724,36.977 77.724,36.173 ccw(c79.583,36.173)
LODRV on Top Layer "NONET_L01_P-001" (solid, pour order 12): 55.491,41.037 55.342,41.037 55.342,40.275 55.342,38.878 58.771,38.878 ccw(c58.771,39.64) 59.533,39.64 59.533,44.847 ccw(c58.898,44.847) 58.898,45.482 57.628,45.482 57.628,43.122 cw(c56.275,43.121) 57.232,42.165 56.538,41.471 cw(c55.491,42.517)
NetC16_2 on Top Layer "NONET_L01_P-001" (solid, pour order 21): 61.587,17.034 61.953,17.4 cw(c63.216,16.136) 63.216,17.923 64,17.923 64,18.685 61.819,18.685 ccw(c61.819,16.898) 60.556,18.162 60.459,18.065 cw(c59.196,19.329) 59.196,17.542 57.142,17.542 ccw(c57.142,17.034) 56.634,17.034 56.634,13.605 ccw(c57.015,13.605) 57.015,13.224 57.926,13.224 cw(c57.926,12.357) 58.539,12.97 ccw(c59.152,13.583) 59.152,12.716 60.571,12.716 60.571,14.24 61.153,14.822 ccw(c60.107,15.869) 61.587,15.869
NetD3_2 on Top Layer "NONET_L01_P-001" (solid, pour order 25): 32.399,14.091 cw(c33.678,15.37) 31.869,15.37 31.869,25.162 38.092,25.162 38.092,21.024 cw(c36.739,21.023) 37.696,20.067 36.568,18.939 36.568,14.621 ccw(c37.838,14.621) 37.838,13.351 38.854,13.351 38.854,12.589 36.546,12.589 cw(c36.546,14.069) 35.499,13.023 ccw(c35.013,12.537) 35.013,13.224 34.492,13.224 cw(c34.492,16.185)
NetD4_1 on Top Layer "NONET_L01_P-001" (solid, pour order 27): 38.6,25.162 38.6,20.008 cw(c37.247,20.008) 38.204,19.051 ccw(c39.699,17.555) 37.584,17.555 37.584,14.367 41.385,14.367 ccw(c41.385,15.922) 42.484,14.822 cw(c43.225,14.082) 43.225,15.129 44.823,15.129 44.823,16.145 43.965,16.145 cw(c43.965,18.979) 41.961,16.975 cw(c42.717,17.731) 41.648,17.731 41.648,24.4 ccw(c40.886,24.4) 40.886,25.162
NetD3_1 on Top Layer "NONET_L01_P-001" (solid, pour order 28): 25.963,23.32 27.218,23.321 ccw(c27.218,24.584) 28.112,23.691 cw(c29.518,22.285) 29.518,24.273 30.345,24.273 cw(c30.345,23.892) 30.726,23.892 30.726,19.32 cw(c29.837,19.32) 29.837,18.431 27.477,18.431 cw(c27.477,19.784) 26.52,18.827 26.259,19.088 cw(c28.046,20.875) 25.519,20.875 25.519,22.876 cw(c25.963,22.876)
NetC1_5 on Top Layer "NONET_L01_P-001" (solid, pour order 30): 22.725,16.899 22.725,12.462 12.692,12.462 cw(c12.692,15.002) 10.152,15.002 10.152,15.129 cw(c12.438,15.129) 12.438,17.415 22.209,17.415 cw(c22.209,16.899)
V_SOLAR on Top Layer "NONET_L01_P-001" (solid, pour order 33): 36.367,42.762 39.542,42.762 39.616,42.688 39.616,41.545 36.949,41.545 ccw(c36.949,40.529) 35.933,40.529 35.933,39.386 35.425,39.386 35.425,40.222 ccw(c34.556,40.222) 35.17,40.837 35.113,40.894 ccw(c33.235,39.016) 33.235,41.672 25.773,41.672 25.773,43.853 cw(c27.867,43.853) 26.386,45.333 28.611,47.558 ccw(c25.65,50.518) 29.837,50.518 29.837,51.114 ccw(c26.877,51.114) 28.97,53.207 28.418,53.759 ccw(c26.938,52.279) 26.938,54.372 24.565,54.372 ccw(c24.564,49.318) 20.991,52.892 20.339,52.24 cw(c13.835,58.744) 13.835,49.546 cw(c13.835,53.102) 10.279,53.102 10.279,53.61 cw(c14.343,53.61) 14.343,57.674 35.425,57.674 35.425,43.704 ccw(c36.367,43.704)
NetC4_2 on Top Layer "NONET_L01_P-001" (solid, pour order 35): 22.979,39.132 34.79,39.132 34.79,35.957 24.376,35.957 cw(c24.376,37.354) 22.979,37.354
NetR8_2 on Top Layer "NONET_L01_P-001" (solid, pour order 38): 62.222,8.017 62.222,4.969 61.333,4.08 61.714,3.699 62.095,4.08 63.492,4.08 64.239,4.827 cw(c65.502,3.563) 65.502,5.35 66.667,5.35 66.667,6.112 65.524,6.112 cw(c65.524,7.952) 64.223,6.651 63.238,7.636 63.238,8.017
GND on Top Layer "NONET_L01_P-001" (solid, pour order 40): 44.615,44.166 ccw(c46.343,45.894) 46.343,43.45 46.728,43.45 46.728,37.608 42.791,37.608 42.791,39.64 44.284,41.133 ccw(c43.597,41.821) 44.569,41.821 ccw(c42.782,41.821) 44.046,43.084 43.733,43.397 ccw(c42.686,42.351) 42.686,43.831 37.667,43.831 cw(c37.667,44.952) 36.875,44.159 cw(c37.921,45.206) 36.441,45.206 36.441,46.117 43.807,46.117 ccw(c46.566,46.117)
MPPSET on Top Layer "NONET_L01_P-001" (solid, pour order 41): 42.029,43.323 43.807,43.323 43.807,41.418 43.172,40.783 42.156,40.783 41.648,40.275 41.648,37.608 38.219,37.608 38.092,37.735 37.584,37.735 37.584,40.91 41.013,40.91 42.029,41.926
GND on Top Layer "NONET_L01_P-001" (solid, pour order 42): 55.491,27.829 55.491,25.289 55.364,25.416 51.046,25.416 49.522,26.94 49.522,27.829
PH on Bottom Layer "NONET_L01_P-001" (solid, pour order 39): 80.954,48.917 86.661,43.21 cw(c84.007,40.557) 87.76,40.557 87.76,36.449 75.822,36.449 75.822,40.767 75.822,49.477 79.602,49.477 cw(c79.602,47.565)
SRP on Bottom Layer "NONET_L01_P-001" (solid, pour order 44): 76.454,19.304 76.454,31.242 87.376,31.242 87.376,19.304
GND on Bottom Layer "NONET_L01_P-001" (solid, remove dead copper, pour order 45): 90.035,58.436 0.119,58.436 0.119,0.016 90.035,0.016
no net on Bottom Solder "NONET_L01_P-001" (solid): 69.982,54.34 49.916,54.34 49.916,34.274 69.982,34.274
V_LOAD on Top Solder "NONET_L01_P-001" (solid): 18.288,22.352 18.288,19.304 22.606,19.304 22.606,22.352
V_BATT on Top Solder "NONET_L01_P-001" (solid): 18.288,22.86 22.606,22.86 25.654,25.908 18.288,25.908

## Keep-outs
Keep-Out Layer:
  the board outline again, w0.254

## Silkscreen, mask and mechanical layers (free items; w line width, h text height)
Top Overlay:
  lines w0.127: 45.458,43.45 36.06,43.45 36.06,33.163 36.06,26.559 39.743,26.559 39.743,33.29 39.743,38.497 45.585,38.497
  text "SOLAR+" at 2.19,52.483 h1.52
  text "SOLAR-" at 2.19,42.965 h1.52
  text "BAT+" at 2.19,33.448 h1.52
  text "BAT-" at 2.19,23.93 h1.52
  text "LOAD+" at 2.19,14.413 h1.52
  text "LOAD-" at 2.19,4.895 h1.52
Bottom Overlay:
  drawing of 592 lines, arcs and shapes, not listed
  text "V_Batt" at 20.448,36.424 h0.76 r180
  text "1S" at 27.369,32.741 h0.76 r180
  text "3S" at 32.385,32.741 h0.76 r180
  text "LA" at 37.465,32.741 h0.76 r180
  text "CHARGER.PROTECTION_V5.0_161225" at 46.355,30.988 h1 r180
  text "V_Solar" at 20.448,30.074 h0.76 r180
  text "6V" at 27.305,26.391 h0.76 r180
  text "9V" at 32.385,26.391 h0.76 r180
  text "12V" at 37.148,26.391 h0.76 r180
  text "17V" at 42.228,26.391 h0.76 r180
  text "RESET" at 73.152,14.986 h1 r180
  text "CHARGE / /DONE" at 58.679,14.816 h1 r180
  text "LOAD" at 51.125,14.434 h1 r180
Bottom Solder:
  pour cut-out: 50.411,40.402 ccw(c51.173,40.402) 51.173,39.64 51.979,39.64 ccw(c51.979,42.601) 54.072,40.507 55.984,42.419 cw(c56.94,41.462) 56.941,42.815 65.038,42.815 cw(c65.038,41.028) 66.301,42.292 68.547,40.046 ccw(c68.594,40.656) 69.027,41.09 66.847,43.27 ccw(c65.8,42.224) 65.8,43.704 58.136,43.704 cw(c58.136,44.571) 57.847,43.754 cw(c58.009,44.212) 57.575,43.994 ccw(c56.603,43.506) 56.603,44.593 55.723,44.593 ccw(c55.723,42.5) 54.243,43.98 53.446,43.183 ccw(c54.642,41.988) 52.951,41.988 52.951,41.418 52.697,41.164 51.173,41.164 ccw(c51.173,40.402)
